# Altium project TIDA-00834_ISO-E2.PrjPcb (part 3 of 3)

## Sheet TIDA-00834_ISO-E2_Pg11_Filters.SchDoc: FILTERS and ADC EVM I/P CONNECTOR
size 431 x 279 mm; Date: Not shown in title block; ApprovedBy: Not shown in title block; CheckedBy: Not shown in title block; Author: Not shown in title block; CompanyName: Not shown in title block; DrawnBy: Sreenivasa; Engineer: Not shown in title block; Organization: Not shown in title block; Address1: Not shown in title block; Address2: Not shown in title block; Address3: Not shown in title block; Address4: Not shown in title block; DocumentNumber: 1; Revision: Use project parameter SCH_Rev; SheetNumber: 11; SheetTotal: 12; PageSetup: Record=PageOptions¦CenterHorizontal=True¦CenterVertical=True¦PrintScale=1.00¦XCorrection=1.00¦YCorrection=1.00¦PrintKind=0¦BorderSize=5000000¦LeftOffset=0¦BottomOffset=0¦Orientation=2¦PaperLength=1000¦PaperWidth=1000¦Scale=100¦PaperSource=15¦PrintQuality=600¦MediaType=1¦DitherType=10¦PaperKind=Letter¦PrintScaleMode=1
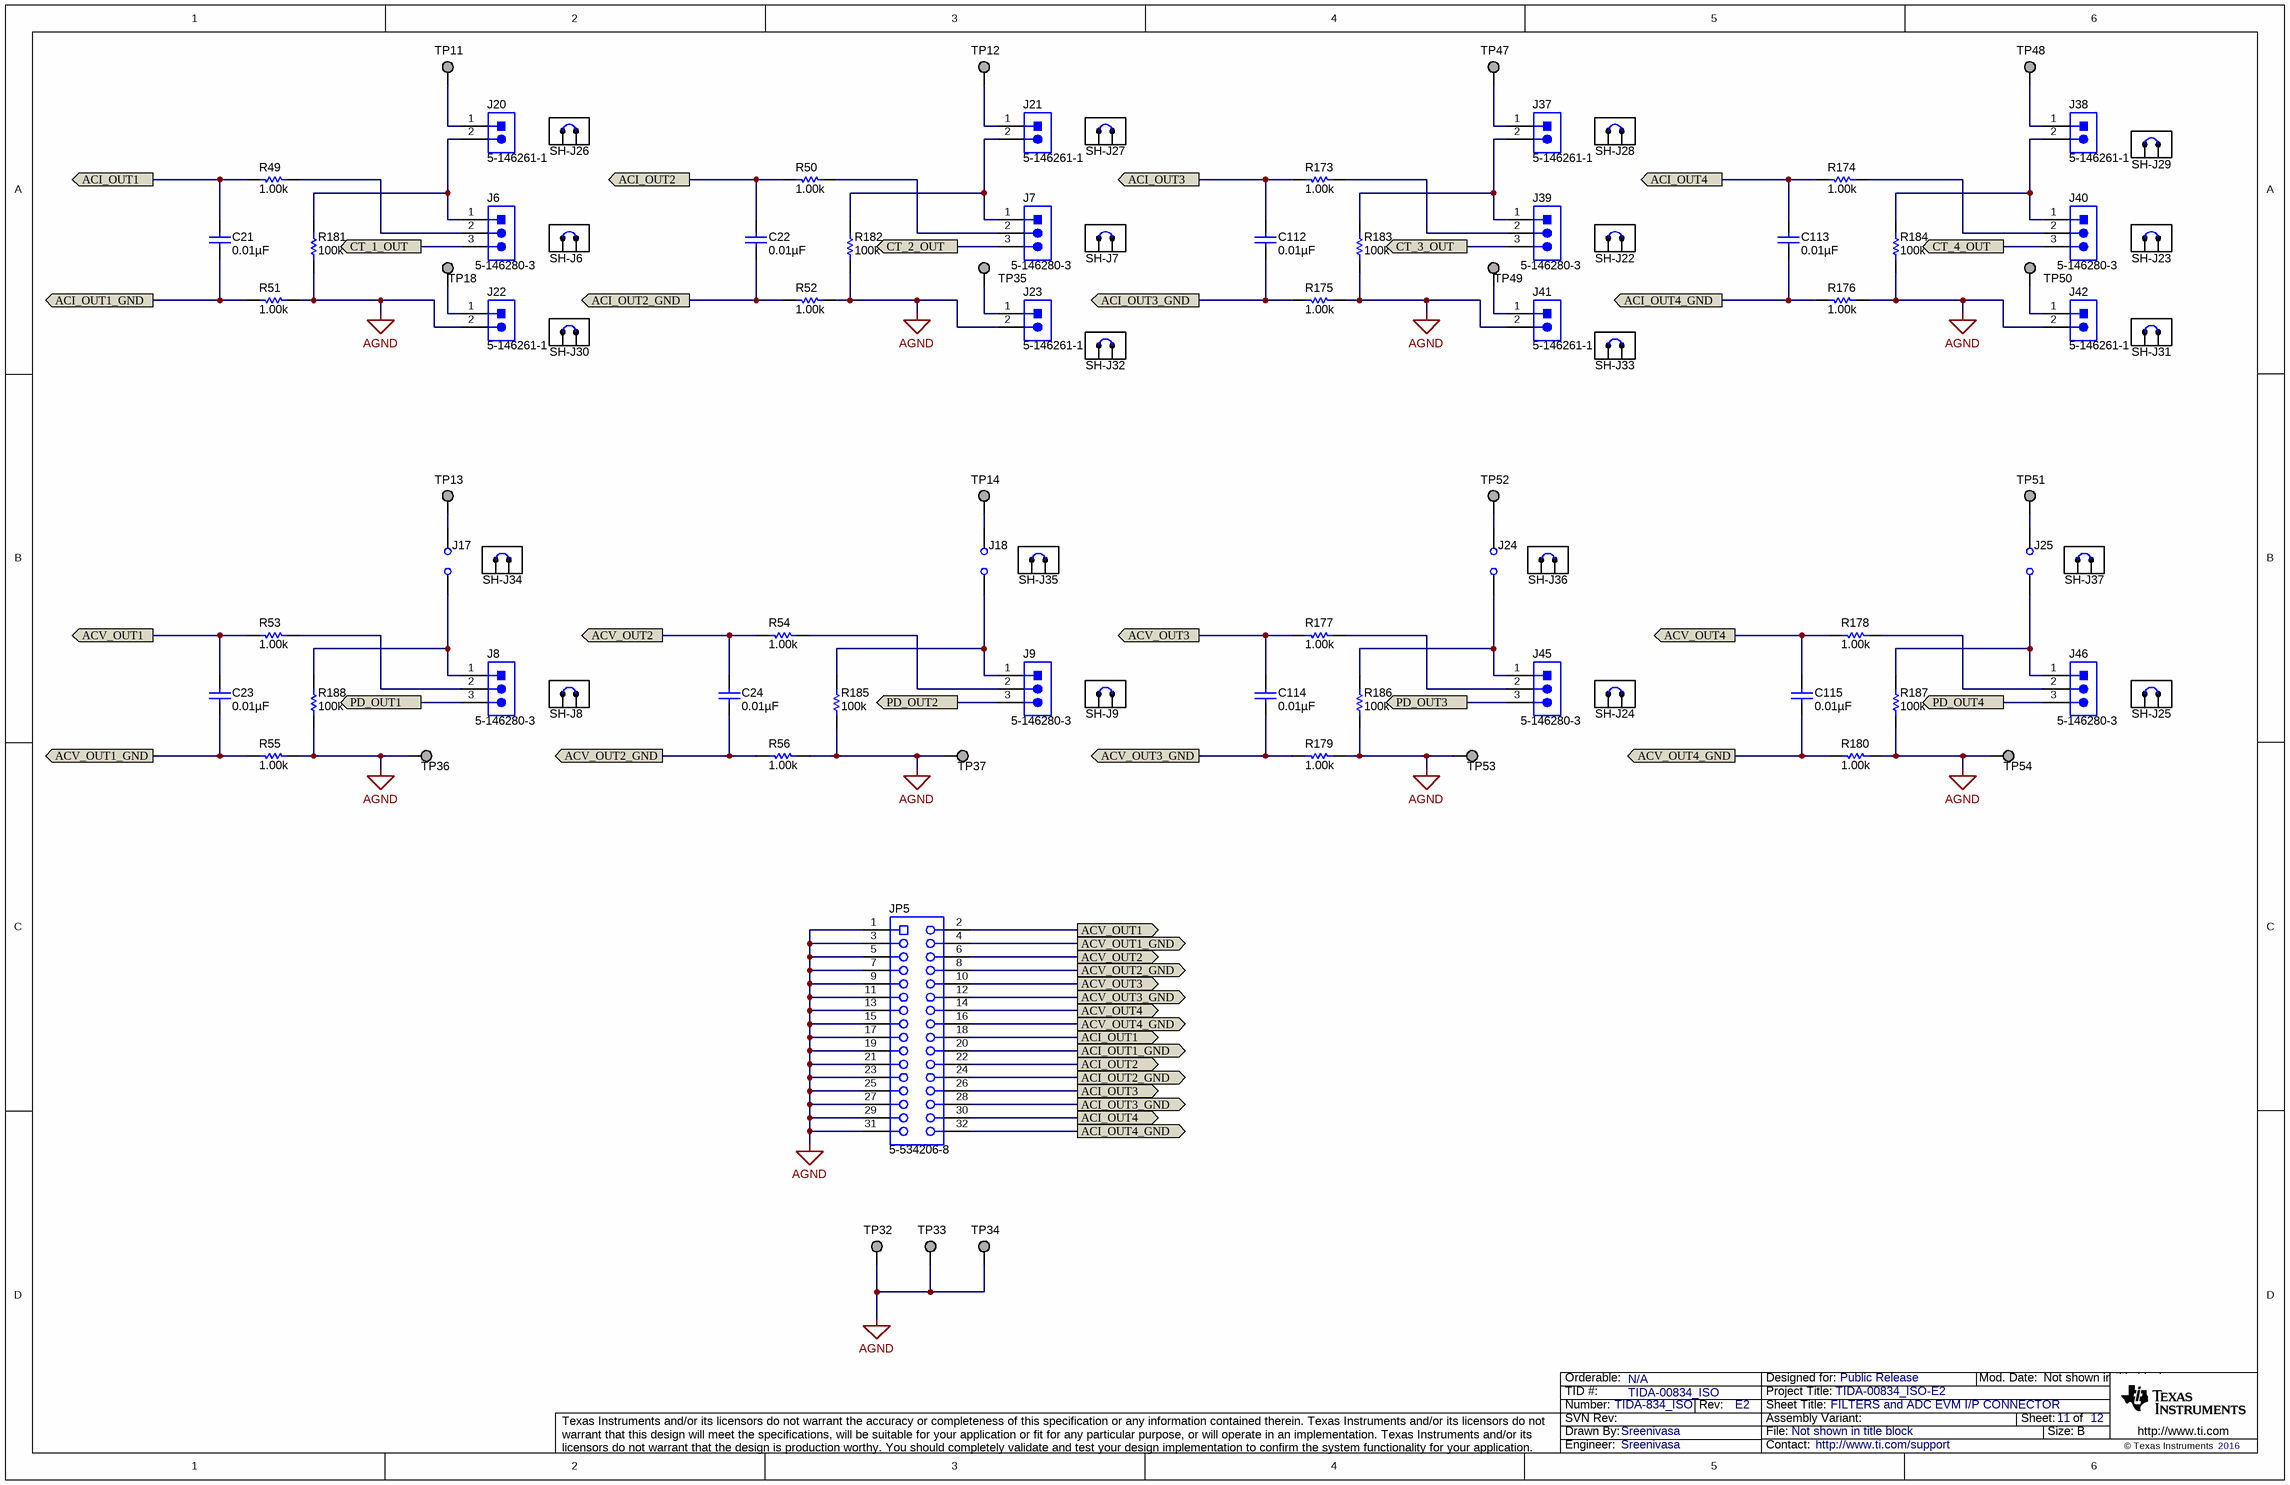
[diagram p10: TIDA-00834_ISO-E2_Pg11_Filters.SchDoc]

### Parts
C21  ValueDisplayed: 0.01µF  [0805_HV]  (hidden comment: C0805C103K5RACTU)
C22  ValueDisplayed: 0.01µF  [0805_HV]  (hidden comment: C0805C103K5RACTU)
C23  ValueDisplayed: 0.01µF  [0805_HV]  (hidden comment: C0805C103K5RACTU)
C24  ValueDisplayed: 0.01µF  [0805_HV]  (hidden comment: C0805C103K5RACTU)
C112  ValueDisplayed: 0.01µF  [0805_HV]  (hidden comment: C0805C103K5RACTU)
C113  ValueDisplayed: 0.01µF  [0805_HV]  (hidden comment: C0805C103K5RACTU)
C114  ValueDisplayed: 0.01µF  [0805_HV]  (hidden comment: C0805C103K5RACTU)
C115  ValueDisplayed: 0.01µF  [0805_HV]  (hidden comment: C0805C103K5RACTU)
J6  5-146280-3  [TE_5-146280-3]
J7  5-146280-3  [TE_5-146280-3]
J8  5-146280-3  [TE_5-146280-3]
J9  5-146280-3  [TE_5-146280-3]
J17  JUMPER_2X100MIL  [HDR100_1X2]  (value not drawn)
J18  JUMPER_2X100MIL  [HDR100_1X2]  (value not drawn)
J20  5-146261-1  [CONN_5-146261-1]
J21  5-146261-1  [CONN_5-146261-1]
J22  5-146261-1  [CONN_5-146261-1]
J23  5-146261-1  [CONN_5-146261-1]
J24  JUMPER_2X100MIL  [HDR100_1X2]  (value not drawn)
J25  JUMPER_2X100MIL  [HDR100_1X2]  (value not drawn)
J37  5-146261-1  [CONN_5-146261-1]
J38  5-146261-1  [CONN_5-146261-1]
J39  5-146280-3  [TE_5-146280-3]
J40  5-146280-3  [TE_5-146280-3]
J41  5-146261-1  [CONN_5-146261-1]
J42  5-146261-1  [CONN_5-146261-1]
J45  5-146280-3  [TE_5-146280-3]
J46  5-146280-3  [TE_5-146280-3]
JP5  5-534206-8  [Samtec_SSW-116-01-x-D]
R49  ValueDisplayed: 1.00k  [0805_HV]  (hidden comment: CRCW08051K00FKEA)
R50  ValueDisplayed: 1.00k  [0805_HV]  (hidden comment: CRCW08051K00FKEA)
R51  ValueDisplayed: 1.00k  [0805_HV]  (hidden comment: CRCW08051K00FKEA)
R52  ValueDisplayed: 1.00k  [0805_HV]  (hidden comment: CRCW08051K00FKEA)
R53  ValueDisplayed: 1.00k  [0805_HV]  (hidden comment: CRCW08051K00FKEA)
R54  ValueDisplayed: 1.00k  [0805_HV]  (hidden comment: CRCW08051K00FKEA)
R55  ValueDisplayed: 1.00k  [0805_HV]  (hidden comment: CRCW08051K00FKEA)
R56  ValueDisplayed: 1.00k  [0805_HV]  (hidden comment: CRCW08051K00FKEA)
R173  ValueDisplayed: 1.00k  [0805_HV]  (hidden comment: CRCW08051K00FKEA)
R174  ValueDisplayed: 1.00k  [0805_HV]  (hidden comment: CRCW08051K00FKEA)
R175  ValueDisplayed: 1.00k  [0805_HV]  (hidden comment: CRCW08051K00FKEA)
R176  ValueDisplayed: 1.00k  [0805_HV]  (hidden comment: CRCW08051K00FKEA)
R177  ValueDisplayed: 1.00k  [0805_HV]  (hidden comment: CRCW08051K00FKEA)
R178  ValueDisplayed: 1.00k  [0805_HV]  (hidden comment: CRCW08051K00FKEA)
R179  ValueDisplayed: 1.00k  [0805_HV]  (hidden comment: CRCW08051K00FKEA)
R180  ValueDisplayed: 1.00k  [0805_HV]  (hidden comment: CRCW08051K00FKEA)
R181  ValueDisplayed: 100k  [0805_HV]  (hidden comment: CRCW0805100KFKEA)
R182  ValueDisplayed: 100k  [0805_HV]  (hidden comment: CRCW0805100KFKEA)
R183  ValueDisplayed: 100k  [0805_HV]  (hidden comment: CRCW0805100KFKEA)
R184  ValueDisplayed: 100k  [0805_HV]  (hidden comment: CRCW0805100KFKEA)
R185  ValueDisplayed: 100k  [0805_HV]  (hidden comment: CRCW0805100KFKEA)
R186  ValueDisplayed: 100k  [0805_HV]  (hidden comment: CRCW0805100KFKEA)
R187  ValueDisplayed: 100k  [0805_HV]  (hidden comment: CRCW0805100KFKEA)
R188  ValueDisplayed: 100k  [0805_HV]  (hidden comment: CRCW0805100KFKEA)
SH-J6  881545-2  [TE_881545-2]  (value not drawn)  (mechanical)
SH-J7  881545-2  [TE_881545-2]  (value not drawn)  (mechanical)
SH-J8  881545-2  [TE_881545-2]  (value not drawn)  (mechanical)
SH-J9  881545-2  [TE_881545-2]  (value not drawn)  (mechanical)
SH-J22  881545-2  [TE_881545-2]  (value not drawn)  (mechanical)
SH-J23  881545-2  [TE_881545-2]  (value not drawn)  (mechanical)
SH-J24  881545-2  [TE_881545-2]  (value not drawn)  (mechanical)
SH-J25  881545-2  [TE_881545-2]  (value not drawn)  (mechanical)
SH-J26  881545-2  [TE_881545-2]  (value not drawn)  (mechanical)
SH-J27  881545-2  [TE_881545-2]  (value not drawn)  (mechanical)
SH-J28  881545-2  [TE_881545-2]  (value not drawn)  (mechanical)
SH-J29  881545-2  [TE_881545-2]  (value not drawn)  (mechanical)
SH-J30  881545-2  [TE_881545-2]  (value not drawn)  (mechanical)
SH-J31  881545-2  [TE_881545-2]  (value not drawn)  (mechanical)
SH-J32  881545-2  [TE_881545-2]  (value not drawn)  (mechanical)
SH-J33  881545-2  [TE_881545-2]  (value not drawn)  (mechanical)
SH-J34  881545-2  [TE_881545-2]  (value not drawn)  (mechanical)
SH-J35  881545-2  [TE_881545-2]  (value not drawn)  (mechanical)
SH-J36  881545-2  [TE_881545-2]  (value not drawn)  (mechanical)
SH-J37  881545-2  [TE_881545-2]  (value not drawn)  (mechanical)
TP11  Suggest using a net name here  [Keystone1573-2]  (value not drawn)
TP12  Suggest using a net name here  [Keystone1573-2]  (value not drawn)
TP13  Suggest using a net name here  [Keystone1573-2]  (value not drawn)
TP14  Suggest using a net name here  [Keystone1573-2]  (value not drawn)
TP18  Suggest using a net name here  [Keystone1573-2]  (value not drawn)
TP32  Suggest using a net name here  [Keystone1573-2]  (value not drawn)
TP33  Suggest using a net name here  [Keystone1573-2]  (value not drawn)
TP34  Suggest using a net name here  [Keystone1573-2]  (value not drawn)
TP35  Suggest using a net name here  [Keystone1573-2]  (value not drawn)
TP36  Suggest using a net name here  [Keystone1573-2]  (value not drawn)
TP37  Suggest using a net name here  [Keystone1573-2]  (value not drawn)
TP47  Suggest using a net name here  [Keystone1573-2]  (value not drawn)
TP48  Suggest using a net name here  [Keystone1573-2]  (value not drawn)
TP49  Suggest using a net name here  [Keystone1573-2]  (value not drawn)
TP50  Suggest using a net name here  [Keystone1573-2]  (value not drawn)
TP51  Suggest using a net name here  [Keystone1573-2]  (value not drawn)
TP52  Suggest using a net name here  [Keystone1573-2]  (value not drawn)
TP53  Suggest using a net name here  [Keystone1573-2]  (value not drawn)
TP54  Suggest using a net name here  [Keystone1573-2]  (value not drawn)

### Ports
ACI_OUT1 (out), ACI_OUT1_GND (out), ACI_OUT2 (out), ACI_OUT2_GND (out), ACI_OUT3 (out), ACI_OUT3_GND (out), ACI_OUT4 (out), ACI_OUT4_GND (out), ACV_OUT1 (out), ACV_OUT1_GND (out), ACV_OUT2 (out), ACV_OUT2_GND (out), ACV_OUT3 (out), ACV_OUT3_GND (out), ACV_OUT4 (out), ACV_OUT4_GND (out), CT_1_OUT (out), CT_2_OUT (out), CT_3_OUT (out), CT_4_OUT (out), PD_OUT1 (out), PD_OUT2 (out), PD_OUT3 (out), PD_OUT4 (out)

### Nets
AGND: J22.2 J23.2 J41.2 J42.2 JP5.1 JP5.3 JP5.5 JP5.7 JP5.9 JP5.11 JP5.13 JP5.15 JP5.17 JP5.19 JP5.21 JP5.23 JP5.25 JP5.27 JP5.29 JP5.31 R51.1 R52.1 R55.1 R56.1 R175.1 R176.1 R179.1 R180.1 R181.1 R182.1 R183.1 R184.1 R185.1 R186.1 R187.1 R188.1 TP32.1 TP33.1 TP34.1 TP36.1 TP37.1 TP53.1 TP54.1
ACI_OUT1: C21.1 JP5.18 R49.2 ; port ACI_OUT1
ACI_OUT1_GND: C21.2 JP5.20 R51.2 ; port ACI_OUT1_GND
ACI_OUT2: C22.1 JP5.22 R50.2 ; port ACI_OUT2
ACI_OUT2_GND: C22.2 JP5.24 R52.2 ; port ACI_OUT2_GND
ACI_OUT3: C112.1 JP5.26 R173.2 ; port ACI_OUT3
ACI_OUT3_GND: C112.2 JP5.28 R175.2 ; port ACI_OUT3_GND
ACI_OUT4: C113.1 JP5.30 R174.2 ; port ACI_OUT4
ACI_OUT4_GND: C113.2 JP5.32 R176.2 ; port ACI_OUT4_GND
ACV_OUT1: C23.1 JP5.2 R53.2 ; port ACV_OUT1
ACV_OUT1_GND: C23.2 JP5.4 R55.2 ; port ACV_OUT1_GND
ACV_OUT2: C24.1 JP5.6 R54.2 ; port ACV_OUT2
ACV_OUT2_GND: C24.2 JP5.8 R56.2 ; port ACV_OUT2_GND
ACV_OUT3: C114.1 JP5.10 R177.2 ; port ACV_OUT3
ACV_OUT3_GND: C114.2 JP5.12 R179.2 ; port ACV_OUT3_GND
ACV_OUT4: C115.1 JP5.14 R178.2 ; port ACV_OUT4
ACV_OUT4_GND: C115.2 JP5.16 R180.2 ; port ACV_OUT4_GND
CT_1_OUT: J6.3 ; port CT_1_OUT
CT_2_OUT: J7.3 ; port CT_2_OUT
CT_3_OUT: J39.3 ; port CT_3_OUT
CT_4_OUT: J40.3 ; port CT_4_OUT
PD_OUT1: J8.3 ; port PD_OUT1
PD_OUT2: J9.3 ; port PD_OUT2
PD_OUT3: J45.3 ; port PD_OUT3
PD_OUT4: J46.3 ; port PD_OUT4
NetJ6_1: J6.1 J20.2 R181.2
NetJ6_2: J6.2 R49.1
NetJ7_1: J7.1 J21.2 R182.2
NetJ7_2: J7.2 R50.1
NetJ8_1: J8.1 J17.2 R188.2
NetJ8_2: J8.2 R53.1
NetJ9_1: J9.1 J18.2 R185.2
NetJ9_2: J9.2 R54.1
NetJ17_1: J17.1 TP13.1
NetJ18_1: J18.1 TP14.1
NetJ20_1: J20.1 TP11.1
NetJ21_1: J21.1 TP12.1
NetJ22_1: J22.1 TP18.1
NetJ23_1: J23.1 TP35.1
NetJ24_1: J24.1 TP52.1
NetJ24_2: J24.2 J45.1 R186.2
NetJ25_1: J25.1 TP51.1
NetJ25_2: J25.2 J46.1 R187.2
NetJ37_1: J37.1 TP47.1
NetJ37_2: J37.2 J39.1 R183.2
NetJ38_1: J38.1 TP48.1
NetJ38_2: J38.2 J40.1 R184.2
NetJ39_2: J39.2 R173.1
NetJ40_2: J40.2 R174.1
NetJ41_1: J41.1 TP49.1
NetJ42_1: J42.1 TP50.1
NetJ45_2: J45.2 R177.1
NetJ46_2: J46.2 R178.1

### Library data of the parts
C21-C24 C112-C115 = C0805C103K5RACTU: CAP, CERM, 0.01 µF, 50 V, +/- 10%, X7R, 0805; Manufacturer: Kemet; Polarized: N; CompType: Capacitor; Value: 0.01uF; U/M: EA; Cap_F: 0.00000001; Tolerance_%: 10; ESR_ohm: 1.739; Value1: 1.739 ohm; VDC_V: 50; Value2: 50V; IRMS_A: 0.411; TaMin_C: -55; TaMax_C: 125; Cap_Case: 0805; SizeArea_mm2: 2.5; SizeAreaWB_mm2: 6.75; SizeX_mm: 2; SizeY_mm: 1.25; SizeZ_mm: 1.45; AEC Category: Q200
J6-J9 J39 J40 J45 J46 = 5-146280-3: Header, 2.54mm, 3x1, Gold, TH; Manufacturer: TE Connectivity; SymbolCreator: a0799628; Pitch_mm: 2.54; Gender: Male; Shrouded: N; Row_Count: 1
J17 J18 J24 J25 = JUMPER_2X100MIL: Header, Male 2-pin, 100mil spacing,; Manufacturer: Sullins; PartNumber: PEC02SAAN; area: 20000; Value: PEC02SAAN
J20-J23 J37 J38 J41 J42 = 5-146261-1: Header, 100mil, 2x1, Gold, TH; Manufacturer: TE Connectivity; SymbolCreator: a0412235
JP5 = SSW-116-01-G-D: Receptacle, 2.54mm, 16x2, Gold, TH; Manufacturer: Samtec; SymbolCreator: a0411947; Pitch_mm: 2.54; Gender: Female; Row_Count: 2; Current_A: 6.3; Voltage_V: 550; Cert_CSA: Y
R49-R56 R173-R180 = CRCW08051K00FKEA: RES, 1.00 k, 1%, 0.125 W, 0805; Manufacturer: Vishay-Dale; CompType: Resistor; Value: 1.00k; Res_ohm: 1000; Value_Code: 1k00; Tolerance_%: 1; Power_W: 0.125; Value2: 0.125W; VDC_V: 150; TempCo: 100 ppm/C; SizeArea_mm2: 2.5; SizeX_mm: 2; SizeY_mm: 1.25; SizeZ_mm: 1.45; EIA_Code: E96; U/M: EA; AEC Category: Q200
R181-R188 = CRCW0805100KFKEA: RES, 100 k, 1%, 0.125 W, 0805; Manufacturer: Vishay-Dale; CompType: Resistor; Value: 100k; Res_ohm: 100000; Tolerance_%: 1; Power_W: 0.125; Value2: 0.125W; VDC_V: 150; TempCo: 100 ppm/C; SizeArea_mm2: 2.5; SizeX_mm: 2; SizeY_mm: 1.25; SizeZ_mm: 1.45; EIA_Code: E96; U/M: EA; AEC Category: Q200
SH-J6-SH-J9 SH-J22-SH-J37 = 881545-2: Shunt, 100mil, Gold plated, Black; Manufacturer: TE Connectivity
TP11-TP14 TP18 TP32-TP37 TP47-TP54 = 1573-2: Terminal, Turret, TH, Double; Manufacturer: Keystone; CompType: Turret Terminal; U/M: EA

## Sheet TIDA-00834_ISO-E2_Pg12_EVM_Hardware.SchDoc: EVM_Hardware
size 431 x 279 mm; Date: Not shown in title block; ApprovedBy: Not shown in title block; CheckedBy: Not shown in title block; Author: Not shown in title block; CompanyName: Not shown in title block; DrawnBy: Sreenivasa; Engineer: Not shown in title block; Organization: Not shown in title block; Address1: Not shown in title block; Address2: Not shown in title block; Address3: Not shown in title block; Address4: Not shown in title block; DocumentNumber: 1; Revision: Use project parameter SCH_Rev; SheetNumber: 12; SheetTotal: 12; PageSetup: Record=PageOptions¦CenterHorizontal=True¦CenterVertical=True¦PrintScale=1.00¦XCorrection=1.00¦YCorrection=1.00¦PrintKind=0¦BorderSize=5000000¦LeftOffset=0¦BottomOffset=0¦Orientation=2¦PaperLength=1000¦PaperWidth=1000¦Scale=100¦PaperSource=15¦PrintQuality=600¦MediaType=1¦DitherType=10¦PaperKind=Letter¦PrintScaleMode=1
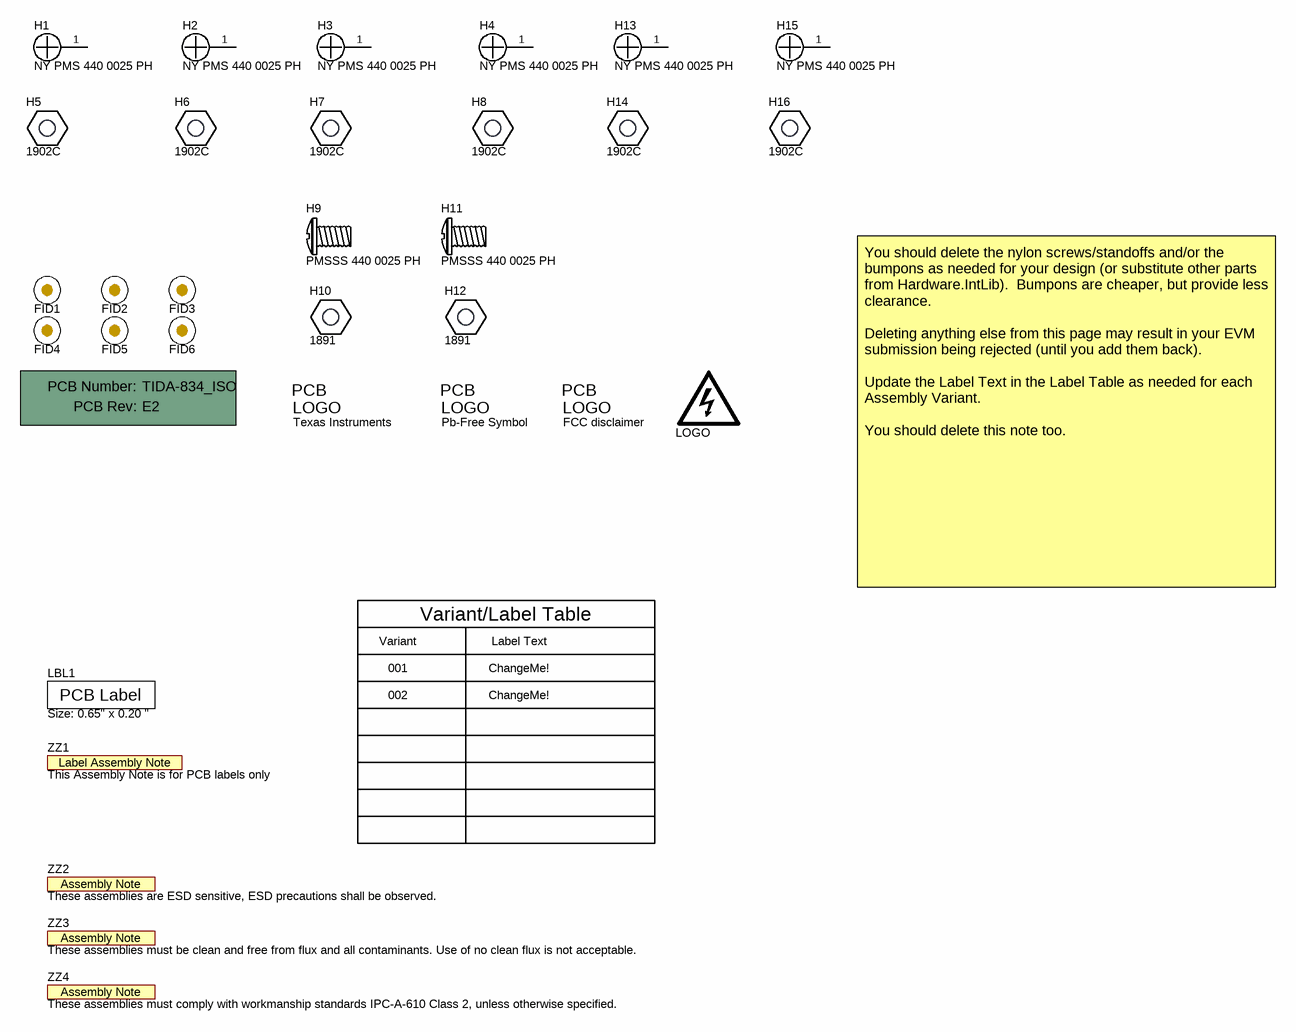
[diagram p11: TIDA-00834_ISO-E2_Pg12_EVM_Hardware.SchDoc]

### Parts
!PCB1  Printed Circuit Board  (value not drawn)  (mechanical)
FID1  Fiducial  [Fiducial10-20]  (value not drawn)
FID2  Fiducial  [Fiducial10-20]  (value not drawn)
FID3  Fiducial  [Fiducial10-20]  (value not drawn)
FID4  Fiducial  [Fiducial10-20]  (value not drawn)
FID5  Fiducial  [Fiducial10-20]  (value not drawn)
FID6  Fiducial  [Fiducial10-20]  (value not drawn)
H1  NY PMS 440 0025 PH  [NY PMS 440 0025 PH]
H2  NY PMS 440 0025 PH  [NY PMS 440 0025 PH]
H3  NY PMS 440 0025 PH  [NY PMS 440 0025 PH]
H4  NY PMS 440 0025 PH  [NY PMS 440 0025 PH]
H5  1902C  [Keystone_1902C]
H6  1902C  [Keystone_1902C]
H7  1902C  [Keystone_1902C]
H8  1902C  [Keystone_1902C]
H9  PMSSS 440 0025 PH  [B_F_PMSSS4400025PH]
H10  1891  [Keystone_1891]
H11  PMSSS 440 0025 PH  [B_F_PMSSS4400025PH]
H12  1891  [Keystone_1891]
H13  NY PMS 440 0025 PH  [NY PMS 440 0025 PH]
H14  1902C  [Keystone_1902C]
H15  NY PMS 440 0025 PH  [NY PMS 440 0025 PH]
H16  1902C  [Keystone_1902C]
LBL1  Size: 0.65" x 0.20 "  [Label_650x200]
LOGO  DANGER HIGH VOLTAGE  [IEC_HighVoltage_Large]  (value not drawn)  (no BOM)
Logo1  Texas Instruments  [TI_Stacked_Overlay_Small]  (no BOM)
Logo2  Pb-Free Symbol  [Pb-Free_Overlay_Small]  (no BOM)
Logo3  FCC disclaimer  [FCC_disclaimer]  (no BOM)
ZZ1  This Assembly Note is for PCB labels only  [AssemblyNoteLabel]  (no BOM)
ZZ2  These assemblies are ESD sensitive, ESD precautions shall be observed.  [AssemblyNote]  (no BOM)
ZZ3  These assemblies must be clean and free from flux and all contaminants. Use of no clean flux is not acceptable.  [AssemblyNote]  (no BOM)
ZZ4  These assemblies must comply with workmanship standards IPC-A-610 Class 2, unless otherwise specified.  [AssemblyNote]  (no BOM)

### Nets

Not connected (* = marked no-connect by the designer): H1 1; H2 1; H3 1; H4 1; H13 1; H15 1

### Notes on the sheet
- Variant
- Variant/Label Table
- Label Text
- You should delete the nylon screws/standoffs and/or the bumpons as needed for your design (or substitute other parts from Hardware.IntLib).  Bumpons are cheaper, but provide less clearance.
  Deleting anything else from this page may result in your EVM submission being rejected (until you add them back).
  Update the Label Text in the Label Table as needed for each Assembly Variant.
  You should delete this note too.
- 001
- 002
- ChangeMe!

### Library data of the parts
!PCB1 = PCB: Manufacturer: Any; PartNumber: TIDA-834_ISO; SymbolCreator: a0412235
FID1-FID6 = Fiducial: Fiducial mark.  There is nothing to buy or mount.; SymbolCreator: codlsc
H1-H4 H13 H15 = NY PMS 440 0025 PH: Machine Screw, Round, #4-40 x 1/4, Nylon, Philips panhead; Manufacturer: B&F Fastener Supply; CompType: Hardware; SymbolCreator: codlsc; U/M: EA
H5-H8 H14 H16 = 1902C: Standoff, Hex, 0.5"L #4-40 Nylon; Manufacturer: Keystone; CompType: Hardware
H9 H11 = PMSSS 440 0025 PH: MACHINE SCREW PAN PHILLIPS 4-40; Manufacturer: B&F Fastener Supply; SymbolCreator: a0412235; CompType: Standoff
H10 H12 = 1891: Hex Standoff, #4-40, Aluminum, 1/4"; Manufacturer: Keystone; SymbolCreator: a0412235
LBL1 = THT-14-423-10: Thermal Transfer Printable Labels, 0.650" W x 0.200" H - 10,000 per roll; Manufacturer: Brady; SymbolCreator: a0412235; CompType: Label
LOGO = IEC_HighVoltage: IEC 61010-1 High Voltage Warning; SymbolCreator: a0412235
Logo1 = TI_Logo: Texas Instrument Corporate Signature; SymbolCreator: codlsc
Logo2 = Pb-Free: SymbolCreator: a0412235
Logo3 = FCC_disclaimer: SymbolCreator: codlsc
ZZ1 = AssemblyNoteLabel: SymbolCreator: a0412235
ZZ2-ZZ4 = AssemblyNote: SymbolCreator: codlsc

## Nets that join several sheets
+3.3V: TIDA-00834_ISO-E2_Pg7_ COMPARATOR (R25.2 R31.2 R162.2 R168.2), TIDA-00834_ISO-E2_Pg9_LDO (10 pins)
+5.0V_VDC: TIDA-00834_ISO-E2_Pg5_VOLTAGE (12 pins), TIDA-00834_ISO-E2_Pg6_VOLTAGE2 (12 pins), TIDA-00834_ISO-E2_Pg10_ ISOPOWER (D39.1 R226.2 R227.2)
+5V: TIDA-00834_ISO-E2_Pg5_VOLTAGE (6 pins), TIDA-00834_ISO-E2_Pg6_VOLTAGE2 (6 pins), TIDA-00834_ISO-E2_Pg9_LDO (10 pins), TIDA-00834_ISO-E2_Pg10_ ISOPOWER (R228.2)
+12V: TIDA-00834_ISO-E2_Pg3_CT1_CT2 (8 pins), TIDA-00834_ISO-E2_Pg4_CT3_CT4 (8 pins), TIDA-00834_ISO-E2_Pg5_VOLTAGE (C3.2 U1.8), TIDA-00834_ISO-E2_Pg6_VOLTAGE2 (C103.2 U17.8), TIDA-00834_ISO-E2_Pg7_ COMPARATOR (8 pins), TIDA-00834_ISO-E2_Pg8_Split Rail Converter (R198.2 R234.2), TIDA-00834_ISO-E2_Pg9_LDO (13 pins)
+14V: TIDA-00834_ISO-E2_Pg8_Split Rail Converter (J11.1 J15.1 R238.1 R246.1), TIDA-00834_ISO-E2_Pg9_LDO (C57.1 C58.1 D45.1 U8.3)
-12V: TIDA-00834_ISO-E2_Pg3_CT1_CT2 (8 pins), TIDA-00834_ISO-E2_Pg4_CT3_CT4 (8 pins), TIDA-00834_ISO-E2_Pg5_VOLTAGE (C6.2 U1.4), TIDA-00834_ISO-E2_Pg6_VOLTAGE2 (C106.2 U17.4), TIDA-00834_ISO-E2_Pg8_Split Rail Converter (R233.2 R240.2), TIDA-00834_ISO-E2_Pg9_LDO (6 pins)
-14V: TIDA-00834_ISO-E2_Pg8_Split Rail Converter (J12.1 J16.1 R247.1), TIDA-00834_ISO-E2_Pg9_LDO (C67.2 C69.1 U12.5 U12.8)
AGND: TIDA-00834_ISO-E2_Pg3_CT1_CT2 (26 pins), TIDA-00834_ISO-E2_Pg4_CT3_CT4 (26 pins), TIDA-00834_ISO-E2_Pg5_VOLTAGE (12 pins), TIDA-00834_ISO-E2_Pg6_VOLTAGE2 (12 pins), TIDA-00834_ISO-E2_Pg7_ COMPARATOR (R103.1 R172.1), TIDA-00834_ISO-E2_Pg8_Split Rail Converter (R70.1), TIDA-00834_ISO-E2_Pg9_LDO (57 pins), TIDA-00834_ISO-E2_Pg11_Filters (43 pins)
GND: TIDA-00834_ISO-E2_Pg7_ COMPARATOR (10 pins), TIDA-00834_ISO-E2_Pg10_ ISOPOWER (5 pins)
GND_VDC: TIDA-00834_ISO-E2_Pg5_VOLTAGE (21 pins), TIDA-00834_ISO-E2_Pg6_VOLTAGE2 (21 pins), TIDA-00834_ISO-E2_Pg10_ ISOPOWER (11 pins)
VBIAS: TIDA-00834_ISO-E2_Pg3_CT1_CT2 (R47.1 R101.1 U3.5 U13.5), TIDA-00834_ISO-E2_Pg5_VOLTAGE (R14.1 R17.1), TIDA-00834_ISO-E2_Pg9_LDO (J13.2)
VBIASB: TIDA-00834_ISO-E2_Pg4_CT3_CT4 (R120.1 R136.1 U6.5 U15.5), TIDA-00834_ISO-E2_Pg6_VOLTAGE2 (R151.1 R154.1), TIDA-00834_ISO-E2_Pg9_LDO (J47.2)
CT_1_OUT: TIDA-00834_ISO-E2_Pg3_CT1_CT2 (C20.1 R45.2), TIDA-00834_ISO-E2_Pg11_Filters (J6.3)
CT_2_OUT: TIDA-00834_ISO-E2_Pg3_CT1_CT2 (C84.1 R99.2), TIDA-00834_ISO-E2_Pg11_Filters (J7.3)
CT_3_OUT: TIDA-00834_ISO-E2_Pg4_CT3_CT4 (C90.1 R118.2), TIDA-00834_ISO-E2_Pg11_Filters (J39.3)
CT_4_OUT: TIDA-00834_ISO-E2_Pg4_CT3_CT4 (C100.1 R134.2), TIDA-00834_ISO-E2_Pg11_Filters (J40.3)
PD_OUT1: TIDA-00834_ISO-E2_Pg5_VOLTAGE (C4.1 R8.2), TIDA-00834_ISO-E2_Pg11_Filters (J8.3)
PD_OUT1_ZC: TIDA-00834_ISO-E2_Pg5_VOLTAGE (R229.1), TIDA-00834_ISO-E2_Pg7_ COMPARATOR (R26.1)
PD_OUT2: TIDA-00834_ISO-E2_Pg5_VOLTAGE (C5.1 R10.2), TIDA-00834_ISO-E2_Pg11_Filters (J9.3)
PD_OUT2_ZC: TIDA-00834_ISO-E2_Pg5_VOLTAGE (R230.1), TIDA-00834_ISO-E2_Pg7_ COMPARATOR (R32.1)
PD_OUT3: TIDA-00834_ISO-E2_Pg6_VOLTAGE2 (C104.1 R145.2), TIDA-00834_ISO-E2_Pg11_Filters (J45.3)
PD_OUT3_ZC: TIDA-00834_ISO-E2_Pg6_VOLTAGE2 (R200.1), TIDA-00834_ISO-E2_Pg7_ COMPARATOR (R163.1)
PD_OUT4: TIDA-00834_ISO-E2_Pg6_VOLTAGE2 (C105.1 R147.2), TIDA-00834_ISO-E2_Pg11_Filters (J46.3)
PD_OUT4_ZC: TIDA-00834_ISO-E2_Pg6_VOLTAGE2 (R201.1), TIDA-00834_ISO-E2_Pg7_ COMPARATOR (R169.1)

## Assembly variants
001: not fitted FID1 FID2 FID3 FID4 FID5 FID6 R14 R17 R20 R22 R24 R30 R42 R47 R72 R96 R101 R116 R120 R132 R136 R151 R154 R157 R159 R161 R167 R189 R193 R198 R209 R213 R219 R225 R233 R234 R240 R242 R243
